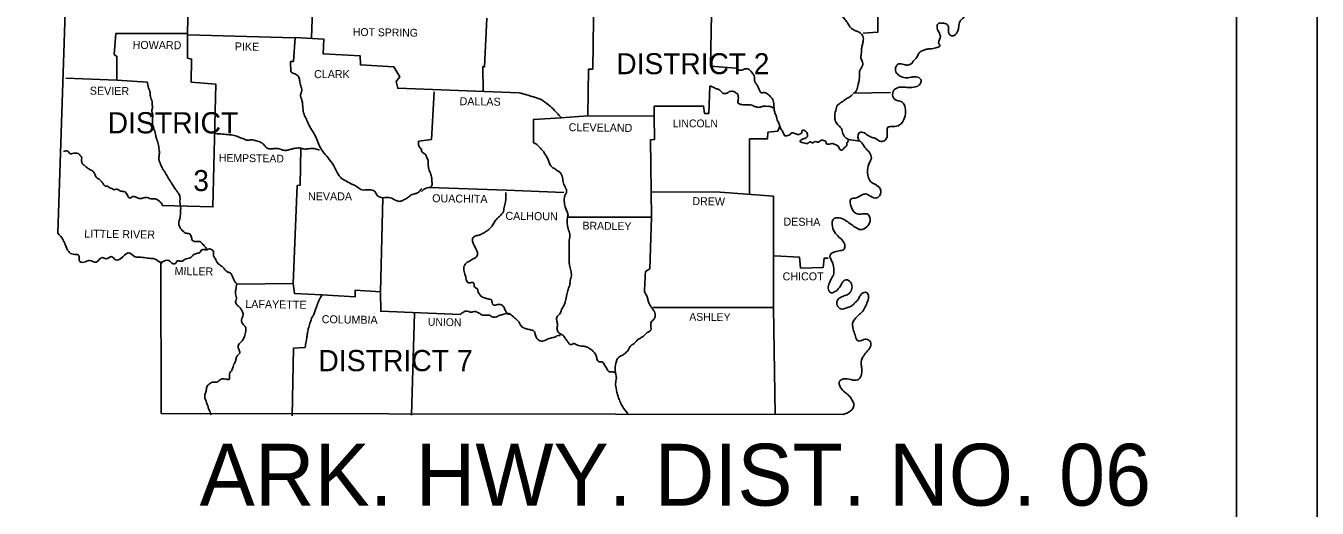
# Model space of a CAD drawing. Extents: x 1367863 to 1368197, y 380048 to 380261.
# Drawn here: x 1368120.7 to 1368196.7, y 380178.3 to 380206.7 of the extents above; entities that cross this region are included whole.
import ezdxf

# ---------------------------------------------------------------- set-up
doc = ezdxf.new("R2010")
doc.units = 0
doc.layers.add('R_Border', color=7, linetype='Continuous')
doc.layers.add('R_No Plot', color=7, linetype='Continuous')

msp = doc.modelspace()

# ---------------------------------------------------------------- linework, layer by layer
at = {"layer": 'R_Border'}
for p, q in [((1368191.969, 380052.084), (1368191.969, 380257.536)), ((1368169.4, 380202.707), (1368171.591, 380202.737)), ((1368169.101, 380199.967), (1368169.788, 380199.877)), ((1368138.078, 380190.782), (1368138.098, 380190.822))]:
    msp.add_line(p, q, dxfattribs=at)
for points in [[(1368123.527, 380224.038), (1368122.546, 380194.468)], [(1368169.987, 380206.243), (1368170.844, 380206.303), (1368170.834, 380208.525), (1368170.037, 380208.585), (1368170.077, 380212.928), (1368169.39, 380213.028), (1368169.36, 380215.957), (1368178.714, 380216.027)], [(1368137.739, 380212.809), (1368137.48, 380205.984)], [(1368130.307, 380211.603), (1368130.187, 380206.214), (1368125.963, 380206.223), (1368125.864, 380204.978), (1368126.023, 380204.869), (1368126.013, 380203.464), (1368123.014, 380203.593)], [(1368154.117, 380208.545), (1368154.057, 380204.121), (1368153.798, 380204.111), (1368153.769, 380201.362)], [(1368161.071, 380208.425), (1368160.981, 380204.301), (1368162.506, 380204.171)], [(1368147.811, 380207.12), (1368147.681, 380204.251), (1368147.582, 380204.281), (1368147.592, 380202.796)], [(1368130.187, 380206.214), (1368130.187, 380204.759), (1368130.427, 380204.709), (1368130.407, 380203.354), (1368131.851, 380203.245), (1368131.682, 380196.002), (1368128.693, 380196.082)], [(1368130.207, 380206.134), (1368136.474, 380205.974)], [(1368136.265, 380203.972), (1368136.245, 380204.57), (1368136.424, 380204.58), (1368136.533, 380205.994), (1368138.217, 380205.885), (1368138.177, 380205.018), (1368140.359, 380204.898), (1368140.369, 380204.37), (1368142.342, 380204.251), (1368142.68, 380203.663), (1368142.471, 380203.394), (1368142.571, 380202.996), (1368149.714, 380202.727)], [(1368126.013, 380203.464), (1368127.826, 380203.354)], [(1368160.951, 380203.125), (1368160.882, 380201.511), (1368160.633, 380201.511), (1368160.583, 380201.94), (1368157.674, 380201.94), (1368157.674, 380201.322)], [(1368144.713, 380202.786), (1368144.553, 380199.967), (1368143.796, 380199.877)], [(1368152.194, 380201.262), (1368150.571, 380201.163), (1368150.561, 380199.788)], [(1368153.769, 380201.362), (1368152.165, 380201.262)], [(1368153.769, 380201.362), (1368157.644, 380201.342)], [(1368157.674, 380201.342), (1368157.684, 380199.967), (1368157.455, 380199.957), (1368157.514, 380195.404)], [(1368165.076, 380200.754), (1368164.946, 380200.465), (1368164.369, 380200.405), (1368164.339, 380200.007), (1368163.293, 380200.007), (1368163.283, 380196.739)], [(1368136.852, 380199.459), (1368136.822, 380197.287), (1368136.633, 380197.257), (1368136.414, 380191.489)], [(1368144.444, 380197.148), (1368148.977, 380196.988), (1368152.344, 380196.859)], [(1368141.684, 380196.54), (1368141.545, 380191.011), (1368140.06, 380191.11), (1368140.05, 380190.712), (1368138.098, 380190.822)], [(1368157.484, 380196.899), (1368161.549, 380196.869), (1368164.707, 380196.63)], [(1368164.707, 380196.63), (1368164.707, 380190.074), (1368164.797, 380183.768)], [(1368152.563, 380195.394), (1368157.514, 380195.404)], [(1368157.514, 380195.404), (1368157.405, 380192.366), (1368157.166, 380192.206)], [(1368128.613, 380192.704), (1368128.633, 380183.838), (1368168.792, 380183.768)], [(1368164.757, 380193.133), (1368166.232, 380193.043), (1368166.291, 380192.406), (1368167.626, 380192.445), (1368167.676, 380192.983), (1368167.925, 380192.983)], [(1368138.098, 380190.822), (1368136.484, 380190.911), (1368136.414, 380191.489), (1368133.086, 380191.449)], [(1368146.237, 380189.676), (1368141.565, 380189.855), (1368141.545, 380190.961)], [(1368143.557, 380189.756), (1368143.378, 380183.738)], [(1368157.584, 380190.084), (1368164.707, 380190.084)], [(1368137.111, 380187.723), (1368136.434, 380187.683), (1368136.354, 380183.708)]]:
    msp.add_lwpolyline(points, dxfattribs=at)
for points in [[(1368178.017, 380213.367), (1368177.768, 380213.058), (1368177.399, 380213.247), (1368177.399, 380213.516), (1368177.449, 380213.785), (1368177.32, 380213.964), (1368177.091, 380213.885), (1368177.091, 380213.546), (1368177.071, 380213.217), (1368177.001, 380212.749), (1368177.15, 380212.599), (1368177.509, 380212.56), (1368177.758, 380212.49), (1368177.907, 380212.241), (1368177.898, 380211.932), (1368177.778, 380211.643), (1368177.609, 380211.394), (1368177.33, 380211.314), (1368177.11, 380211.454), (1368177.021, 380211.743), (1368176.921, 380211.992), (1368176.742, 380212.181), (1368176.543, 380211.972), (1368176.493, 380211.583), (1368176.513, 380211.255), (1368176.513, 380210.806), (1368176.792, 380210.507), (1368176.971, 380210.169), (1368176.911, 380209.86), (1368176.702, 380209.501), (1368176.622, 380209.182), (1368176.533, 380208.754), (1368176.543, 380208.286), (1368176.463, 380207.827), (1368176.314, 380207.519), (1368176.025, 380207.27), (1368175.835, 380207.1), (1368175.686, 380206.941), (1368175.606, 380206.612), (1368175.556, 380206.383), (1368175.347, 380206.104), (1368175.178, 380206.084), (1368175.048, 380206.194), (1368175.008, 380206.383), (1368175.008, 380206.562), (1368174.919, 380206.751), (1368174.65, 380206.831), (1368174.431, 380206.821), (1368174.331, 380206.662), (1368174.47, 380206.233), (1368174.52, 380205.964), (1368174.451, 380205.586), (1368174.49, 380205.546), (1368174.102, 380205.337), (1368173.783, 380205.307), (1368173.514, 380205.227), (1368173.265, 380205.068), (1368173.145, 380204.819), (1368172.966, 380204.63), (1368172.817, 380204.44), (1368172.607, 380204.351)], [(1368166.67, 380209.84), (1368166.7, 380209.392), (1368166.969, 380209.322), (1368167.068, 380209.202), (1368167.128, 380208.953), (1368167.317, 380208.844), (1368167.566, 380208.694), (1368167.716, 380208.585), (1368167.826, 380208.405), (1368167.895, 380208.116), (1368168.075, 380207.937), (1368168.314, 380207.847), (1368168.483, 380207.638), (1368168.593, 380207.339), (1368168.772, 380207.21), (1368168.951, 380206.981), (1368169.031, 380206.881), (1368169.19, 380206.622), (1368169.34, 380206.492), (1368169.449, 380206.413), (1368169.629, 380206.353), (1368169.848, 380206.214), (1368169.987, 380205.994), (1368169.987, 380205.835), (1368169.938, 380205.576), (1368169.888, 380205.317), (1368169.868, 380205.018), (1368169.848, 380204.759), (1368169.948, 380204.54), (1368169.888, 380204.211), (1368169.778, 380204.032), (1368169.768, 380203.793), (1368169.738, 380203.434), (1368169.688, 380203.225), (1368169.599, 380202.886), (1368169.449, 380202.707)], [(1368136.265, 380203.972), (1368136.444, 380203.862), (1368136.653, 380203.763), (1368136.763, 380203.593), (1368136.802, 380203.344), (1368136.882, 380203.065), (1368136.902, 380202.786), (1368136.842, 380202.627), (1368136.922, 380202.278), (1368136.962, 380202.039), (1368136.992, 380201.75), (1368137.081, 380201.372), (1368137.221, 380201.103), (1368137.35, 380200.794), (1368137.57, 380200.445), (1368137.759, 380200.077), (1368137.849, 380199.877), (1368138.008, 380199.479), (1368138.217, 380199.2), (1368138.546, 380198.782), (1368138.845, 380198.353), (1368139.004, 380198.034), (1368139.263, 380197.686), (1368139.542, 380197.516), (1368139.911, 380197.327), (1368140.14, 380197.217), (1368140.399, 380197.028), (1368140.738, 380197.008), (1368140.987, 380197.008), (1368141.226, 380196.909), (1368141.335, 380196.709), (1368141.525, 380196.58), (1368141.684, 380196.54)], [(1368162.506, 380204.171), (1368162.665, 380204.062), (1368162.894, 380204.082), (1368163.054, 380204.141), (1368163.173, 380204.131), (1368163.332, 380204.032), (1368163.442, 380203.902), (1368163.522, 380203.803), (1368163.582, 380203.653), (1368163.582, 380203.504), (1368163.631, 380203.314), (1368163.701, 380203.235), (1368163.781, 380203.095), (1368163.841, 380202.956), (1368163.87, 380202.876), (1368163.99, 380202.727), (1368164.1, 380202.737), (1368164.199, 380202.727), (1368164.339, 380202.657), (1368164.528, 380202.498), (1368164.568, 380202.458), (1368164.697, 380202.169), (1368164.717, 380201.999), (1368164.737, 380201.76), (1368164.787, 380201.541), (1368164.867, 380201.302), (1368164.916, 380201.143), (1368165.016, 380200.913), (1368165.076, 380200.754), (1368165.166, 380200.555), (1368165.295, 380200.336), (1368165.355, 380200.206), (1368165.534, 380200.216)], [(1368172.607, 380204.351), (1368172.378, 380204.39), (1368172.07, 380204.43), (1368171.89, 380204.211), (1368171.95, 380203.892), (1368172.159, 380203.703), (1368172.468, 380203.613), (1368172.787, 380203.643), (1368173.086, 380203.673), (1368173.375, 380203.514), (1368173.325, 380203.225), (1368173.046, 380203.075), (1368172.637, 380203.036), (1368172.309, 380203.065), (1368171.92, 380202.986), (1368171.721, 380202.727), (1368171.83, 380202.348), (1368172.259, 380202.189), (1368172.458, 380201.83), (1368172.468, 380201.491), (1368172.319, 380201.043), (1368172.129, 380200.834), (1368171.741, 380200.744), (1368171.442, 380200.694), (1368171.402, 380200.186), (1368171.273, 380199.937), (1368171.043, 380199.857), (1368170.715, 380200.027), (1368170.515, 380200.097), (1368170.276, 380200.206), (1368169.967, 380200.395), (1368169.738, 380200.366), (1368169.798, 380199.877), (1368169.828, 380199.857), (1368170.087, 380199.499), (1368170.346, 380199.21), (1368170.476, 380198.871)], [(1368127.826, 380203.354), (1368127.886, 380203.026), (1368127.986, 380202.737), (1368127.996, 380202.517), (1368128.095, 380202.189), (1368128.095, 380202.069), (1368128.125, 380201.83), (1368128.085, 380201.701), (1368128.135, 380201.432), (1368128.125, 380201.242), (1368128.125, 380201.073), (1368128.135, 380200.804), (1368128.225, 380200.555), (1368128.314, 380200.196), (1368128.364, 380200.007), (1368128.454, 380199.728), (1368128.514, 380199.379), (1368128.524, 380199.11), (1368128.494, 380198.871), (1368128.564, 380198.602), (1368128.683, 380198.323), (1368128.842, 380198.064), (1368129.022, 380197.765), (1368129.151, 380197.536), (1368129.321, 380197.287), (1368129.45, 380197.078), (1368129.649, 380196.809), (1368129.739, 380196.59), (1368129.739, 380196.281), (1368129.779, 380196.002), (1368129.769, 380195.683), (1368129.749, 380195.394), (1368129.669, 380195.006), (1368129.729, 380194.816), (1368129.938, 380194.548), (1368130.068, 380194.468), (1368130.297, 380194.418), (1368130.407, 380194.269), (1368130.466, 380194.039), (1368130.705, 380193.96), (1368130.955, 380193.94), (1368131.074, 380193.81), (1368131.243, 380193.631), (1368131.293, 380193.541)], [(1368160.951, 380203.125), (1368161.141, 380203.055), (1368161.29, 380202.986), (1368161.469, 380202.916), (1368161.589, 380202.826), (1368161.758, 380202.687), (1368161.958, 380202.707), (1368162.097, 380202.796), (1368162.237, 380202.816), (1368162.346, 380202.806), (1368162.466, 380202.737), (1368162.605, 380202.637), (1368162.625, 380202.498), (1368162.625, 380202.338), (1368162.625, 380202.109), (1368162.705, 380202.069), (1368162.974, 380202.009), (1368163.163, 380202.019), (1368163.332, 380202.019), (1368163.482, 380201.979), (1368163.601, 380201.92), (1368163.691, 380201.9), (1368163.821, 380201.87), (1368163.93, 380201.89), (1368164.119, 380201.93), (1368164.219, 380201.93), (1368164.398, 380201.93), (1368164.508, 380201.92), (1368164.677, 380201.83)], [(1368149.714, 380202.727), (1368150.571, 380202.488), (1368151.009, 380202.328), (1368151.447, 380202.009), (1368151.806, 380201.691), (1368152.165, 380201.282)], [(1368169.38, 380202.637), (1368169.141, 380202.458), (1368168.951, 380202.348), (1368168.742, 380202.189), (1368168.483, 380202.009), (1368168.363, 380201.691), (1368168.304, 380201.252), (1368168.383, 380200.983), (1368168.583, 380200.754), (1368168.722, 380200.575), (1368168.812, 380200.246), (1368169.061, 380200.007), (1368169.131, 380199.977)], [(1368131.831, 380200.326), (1368132.25, 380200.296), (1368132.628, 380200.256), (1368132.927, 380200.216), (1368133.236, 380200.107), (1368133.505, 380200.007), (1368133.684, 380199.937), (1368133.973, 380199.957), (1368134.232, 380199.897), (1368134.511, 380199.808), (1368134.72, 380199.618), (1368134.85, 380199.479), (1368135.109, 380199.419), (1368135.318, 380199.449), (1368135.567, 380199.429), (1368135.856, 380199.339), (1368136.085, 380199.349), (1368136.265, 380199.399), (1368136.484, 380199.449), (1368136.763, 380199.479), (1368136.972, 380199.429), (1368137.241, 380199.419), (1368137.56, 380199.449), (1368137.958, 380199.339)], [(1368165.534, 380200.216), (1368165.674, 380200.276), (1368165.773, 380200.366), (1368165.893, 380200.356), (1368166.022, 380200.306), (1368166.192, 380200.276), (1368166.311, 380200.336), (1368166.361, 380200.385), (1368166.371, 380200.485), (1368166.471, 380200.535), (1368166.58, 380200.465), (1368166.7, 380200.286), (1368166.7, 380200.176), (1368166.66, 380200.107), (1368166.51, 380200.027), (1368166.321, 380199.957), (1368166.261, 380199.877), (1368166.451, 380199.788), (1368166.75, 380199.768), (1368166.819, 380199.838), (1368167.019, 380199.778), (1368167.098, 380199.838), (1368167.357, 380199.828), (1368167.477, 380199.917), (1368167.716, 380199.897), (1368167.796, 380199.848), (1368167.796, 380199.748), (1368167.995, 380199.708), (1368168.134, 380199.738), (1368168.324, 380199.678), (1368168.483, 380199.598), (1368168.573, 380199.479), (1368168.682, 380199.339), (1368168.782, 380199.379), (1368168.862, 380199.479), (1368169.021, 380199.648), (1368169.021, 380199.758), (1368169.071, 380199.838), (1368169.121, 380199.947)], [(1368122.885, 380199.27), (1368123.134, 380199.28), (1368123.293, 380199.13), (1368123.393, 380199.15), (1368123.572, 380199.17), (1368123.732, 380199.16), (1368123.851, 380199.06), (1368123.951, 380198.881), (1368123.941, 380198.722), (1368123.951, 380198.652), (1368124.031, 380198.513), (1368124.16, 380198.403), (1368124.3, 380198.293), (1368124.429, 380198.204), (1368124.648, 380198.064), (1368124.678, 380198.014), (1368124.758, 380197.845), (1368124.867, 380197.696), (1368125.007, 380197.616), (1368125.146, 380197.457), (1368125.206, 380197.397), (1368125.326, 380197.237), (1368125.445, 380197.227), (1368125.605, 380197.128), (1368125.724, 380197.098), (1368125.854, 380197.008), (1368125.993, 380197.048), (1368126.153, 380196.988), (1368126.372, 380196.919), (1368126.491, 380196.899), (1368126.641, 380196.689), (1368126.78, 380196.52), (1368126.95, 380196.61), (1368127.278, 380196.52), (1368127.488, 380196.5), (1368127.677, 380196.56), (1368127.816, 380196.55), (1368128.085, 380196.48), (1368128.245, 380196.48), (1368128.424, 380196.42), (1368128.583, 380196.281), (1368128.693, 380196.142), (1368128.693, 380196.082)], [(1368143.796, 380199.877), (1368143.796, 380199.668), (1368143.876, 380199.479), (1368143.956, 380199.389), (1368143.985, 380199.24), (1368144.085, 380199.18), (1368144.224, 380199.051), (1368144.304, 380198.861), (1368144.354, 380198.742), (1368144.354, 380198.582), (1368144.364, 380198.433), (1368144.394, 380198.244), (1368144.523, 380197.915), (1368144.553, 380197.785), (1368144.573, 380197.676), (1368144.583, 380197.486), (1368144.583, 380197.267), (1368144.444, 380197.148)], [(1368150.561, 380199.788), (1368150.81, 380199.628), (1368151.019, 380199.409), (1368151.168, 380199.24), (1368151.268, 380199.06), (1368151.407, 380198.841), (1368151.587, 380198.423), (1368151.756, 380198.283), (1368151.985, 380198.134), (1368152.125, 380198.034), (1368152.264, 380197.726), (1368152.334, 380197.407), (1368152.453, 380197.118), (1368152.513, 380196.899), (1368152.414, 380196.679), (1368152.384, 380196.241), (1368152.453, 380195.942), (1368152.543, 380195.723), (1368152.593, 380195.474), (1368152.563, 380195.394)], [(1368170.476, 380198.871), (1368170.356, 380198.622), (1368170.236, 380198.184), (1368170.276, 380197.805), (1368170.436, 380197.486), (1368170.705, 380197.317), (1368170.984, 380197.068), (1368170.964, 380196.679), (1368170.794, 380196.54), (1368170.416, 380196.64), (1368170.117, 380196.769), (1368169.868, 380196.689), (1368169.529, 380196.53), (1368169.28, 380196.49), (1368169.29, 380195.972), (1368169.629, 380195.594), (1368169.918, 380195.594), (1368170.266, 380195.554), (1368170.386, 380195.155), (1368170.187, 380194.826), (1368169.858, 380194.667), (1368169.439, 380194.856), (1368169.141, 380195.066), (1368168.852, 380195.265), (1368168.473, 380195.364), (1368168.264, 380195.325), (1368168.164, 380194.856), (1368168.344, 380194.448), (1368168.632, 380194.159), (1368168.891, 380193.79), (1368168.852, 380193.511), (1368168.652, 380193.432), (1368168.304, 380193.362), (1368168.094, 380193.252), (1368168.035, 380193.163), (1368168.144, 380192.794), (1368168.244, 380192.386), (1368168.244, 380192.077), (1368168.124, 380191.788), (1368167.935, 380191.35), (1368167.965, 380191.071), (1368168.094, 380190.941), (1368168.254, 380190.981), (1368168.473, 380191.13), (1368168.623, 380191.31), (1368168.742, 380191.529), (1368168.971, 380191.718), (1368169.25, 380191.549), (1368169.32, 380191.21), (1368169.16, 380190.911), (1368168.921, 380190.782), (1368168.642, 380190.672), (1368168.433, 380190.433), (1368168.483, 380190.144), (1368168.652, 380189.995), (1368169.061, 380190.074), (1368169.33, 380190.194), (1368169.479, 380190.343), (1368169.669, 380190.533), (1368169.768, 380190.722), (1368169.908, 380190.911)], [(1368143.995, 380197.098), (1368143.876, 380196.958), (1368143.736, 380196.829), (1368143.567, 380196.779), (1368143.418, 380196.739), (1368143.218, 380196.6), (1368143.059, 380196.49), (1368142.86, 380196.391), (1368142.66, 380196.331), (1368142.421, 380196.41), (1368142.282, 380196.48), (1368142.142, 380196.54), (1368141.684, 380196.54)], [(1368143.956, 380196.919), (1368144.234, 380197.108), (1368144.553, 380197.148)], [(1368148.937, 380196.859), (1368148.917, 380196.311), (1368148.837, 380195.972), (1368148.757, 380195.663), (1368148.598, 380195.484), (1368148.419, 380195.315), (1368148.259, 380195.115), (1368148.12, 380194.876), (1368147.97, 380194.717), (1368147.781, 380194.567), (1368147.602, 380194.458), (1368147.393, 380194.358), (1368147.163, 380194.298), (1368146.994, 380194.179), (1368146.984, 380193.92), (1368147.173, 380193.541), (1368147.243, 380193.372), (1368147.263, 380193.163), (1368147.183, 380193.043), (1368147.004, 380192.944), (1368146.805, 380192.824), (1368146.615, 380192.714), (1368146.486, 380192.525), (1368146.456, 380192.276), (1368146.546, 380191.977), (1368146.586, 380191.808), (1368146.725, 380191.529), (1368146.835, 380191.539), (1368147.034, 380191.529), (1368147.054, 380191.479), (1368147.064, 380191.419), (1368147.104, 380191.28), (1368147.273, 380191.16), (1368147.293, 380191.051), (1368147.393, 380190.841), (1368147.552, 380190.692), (1368147.681, 380190.652), (1368147.931, 380190.572), (1368148.06, 380190.543), (1368148.2, 380190.224), (1368148.379, 380190.234), (1368148.508, 380190.254), (1368148.728, 380190.204), (1368148.827, 380190.074), (1368148.927, 380189.855), (1368149.056, 380189.696), (1368149.146, 380189.696)], [(1368152.563, 380195.394), (1368152.603, 380194.717), (1368152.703, 380194.388), (1368152.673, 380194.039), (1368152.663, 380193.701), (1368152.663, 380193.392), (1368152.663, 380193.093), (1368152.663, 380192.794), (1368152.683, 380192.575), (1368152.762, 380192.256), (1368152.792, 380191.957), (1368152.732, 380191.668), (1368152.693, 380191.409), (1368152.603, 380191.15), (1368152.533, 380190.851), (1368152.444, 380190.463), (1368152.364, 380190.214), (1368152.214, 380189.955), (1368152.115, 380189.706), (1368151.965, 380189.556), (1368151.935, 380189.297), (1368151.975, 380189.048), (1368151.945, 380188.829), (1368152.025, 380188.63), (1368152.224, 380188.48)], [(1368122.546, 380194.468), (1368122.865, 380194.049), (1368122.995, 380193.751), (1368123.184, 380193.372), (1368123.453, 380193.213), (1368123.772, 380193.163), (1368123.841, 380192.794), (1368124.17, 380192.774), (1368124.429, 380192.854), (1368124.798, 380192.754), (1368125.176, 380193.023), (1368125.395, 380192.954), (1368125.714, 380193.083), (1368125.953, 380192.884), (1368126.372, 380193.063), (1368126.74, 380193.302), (1368127.099, 380193.073), (1368127.438, 380193.043), (1368127.836, 380192.983), (1368128.155, 380192.963), (1368128.444, 380192.824), (1368128.653, 380192.685), (1368128.613, 380192.704)], [(1368128.613, 380192.704), (1368128.992, 380192.864), (1368129.151, 380192.814), (1368129.301, 380192.665), (1368129.46, 380192.665), (1368129.55, 380192.804), (1368129.719, 380192.814), (1368129.849, 380192.804), (1368129.988, 380192.884), (1368130.108, 380192.944), (1368130.277, 380192.993), (1368130.397, 380193.043), (1368130.506, 380193.163), (1368130.705, 380193.262), (1368130.935, 380193.342), (1368130.994, 380193.452), (1368131.104, 380193.491), (1368131.323, 380193.482), (1368131.473, 380193.541), (1368131.592, 380193.491), (1368131.702, 380193.412), (1368131.722, 380193.133), (1368131.811, 380192.973), (1368131.941, 380192.704), (1368132.13, 380192.555), (1368132.299, 380192.416), (1368132.369, 380192.326), (1368132.558, 380192.166), (1368132.718, 380192.107), (1368132.798, 380191.987), (1368132.917, 380191.708), (1368133.086, 380191.449)], [(1368157.166, 380192.206), (1368157.136, 380191.868), (1368157.126, 380191.549), (1368157.106, 380191.24), (1368157.106, 380191.011), (1368157.235, 380190.762), (1368157.305, 380190.523), (1368157.385, 380190.313), (1368157.544, 380190.035), (1368157.684, 380189.835), (1368157.724, 380189.536), (1368157.634, 380189.377), (1368157.475, 380189.148), (1368157.465, 380188.739), (1368157.265, 380188.6), (1368157.016, 380188.381), (1368156.867, 380188.281), (1368156.717, 380188.191), (1368156.548, 380188.012), (1368156.309, 380187.843), (1368156.14, 380187.574), (1368155.94, 380187.365), (1368155.771, 380187.255), (1368155.542, 380187.116), (1368155.442, 380186.896), (1368155.372, 380186.488), (1368155.402, 380186.189), (1368155.442, 380185.93), (1368155.392, 380185.601), (1368155.442, 380185.243), (1368155.502, 380184.954), (1368155.592, 380184.705), (1368155.711, 380184.416), (1368155.861, 380184.157), (1368156.189, 380183.748)], [(1368133.086, 380191.449), (1368133.027, 380191.13), (1368133.017, 380190.881), (1368133.067, 380190.582), (1368133.017, 380190.443), (1368133.096, 380190.234), (1368133.266, 380190.074), (1368133.385, 380189.895), (1368133.465, 380189.646), (1368133.365, 380189.357), (1368133.475, 380189.068), (1368133.575, 380188.959), (1368133.624, 380188.779), (1368133.555, 380188.441), (1368133.455, 380188.191), (1368133.236, 380187.932), (1368133.166, 380187.813), (1368133.196, 380187.653), (1368133.256, 380187.385), (1368133.196, 380187.315), (1368133.057, 380187.125), (1368133.017, 380186.916), (1368132.917, 380186.737), (1368132.808, 380186.418), (1368132.658, 380186.159), (1368132.638, 380185.86), (1368132.419, 380185.86), (1368132.17, 380185.86), (1368131.941, 380185.701), (1368131.732, 380185.691), (1368131.483, 380185.591), (1368131.323, 380185.382), (1368131.273, 380185.153), (1368131.204, 380184.934), (1368131.273, 380184.555), (1368131.373, 380184.296), (1368131.443, 380184.087), (1368131.582, 380183.748)], [(1368169.908, 380190.911), (1368170.167, 380190.971), (1368170.286, 380190.802), (1368170.236, 380190.433), (1368170.087, 380190.084), (1368169.878, 380189.785), (1368169.649, 380189.576), (1368169.36, 380189.128), (1368169.419, 380188.71), (1368169.529, 380188.371), (1368169.679, 380188.112), (1368169.948, 380188.162), (1368170.236, 380188.201), (1368170.416, 380188.052), (1368170.396, 380187.753), (1368170.177, 380187.454), (1368169.967, 380187.165), (1368169.858, 380186.777), (1368169.898, 380186.498), (1368169.898, 380186.249), (1368169.818, 380185.97), (1368169.659, 380185.82), (1368169.25, 380185.83), (1368168.822, 380185.87), (1368168.593, 380185.741), (1368168.642, 380185.372), (1368168.891, 380185.093), (1368169.071, 380184.954), (1368169.32, 380184.645), (1368169.429, 380184.396), (1368169.4, 380184.177), (1368169.24, 380183.987), (1368168.792, 380183.768)], [(1368137.111, 380187.723), (1368137.171, 380188.082), (1368137.221, 380188.351), (1368137.251, 380188.61), (1368137.321, 380188.909), (1368137.42, 380189.228), (1368137.51, 380189.487), (1368137.629, 380189.676), (1368137.699, 380189.895), (1368137.799, 380190.164), (1368137.898, 380190.433), (1368138.078, 380190.782)], [(1368146.237, 380189.676), (1368146.416, 380189.795), (1368146.586, 380189.865), (1368146.745, 380189.835), (1368146.924, 380189.805), (1368147.074, 380189.835), (1368147.273, 380189.795), (1368147.432, 380189.696), (1368147.622, 380189.626), (1368147.811, 380189.626), (1368147.97, 380189.626), (1368148.12, 380189.526), (1368148.379, 380189.536), (1368148.598, 380189.626), (1368148.817, 380189.686), (1368149.116, 380189.726), (1368149.375, 380189.536), (1368149.564, 380189.377), (1368149.714, 380189.208), (1368149.823, 380189.008), (1368149.943, 380188.899), (1368150.142, 380188.819), (1368150.292, 380188.789), (1368150.481, 380188.739), (1368150.581, 380188.69), (1368150.67, 380188.48), (1368150.81, 380188.201), (1368151.089, 380188.102), (1368151.427, 380188.231), (1368151.696, 380188.311), (1368151.896, 380188.371), (1368152.015, 380188.421), (1368152.125, 380188.431), (1368152.095, 380188.451), (1368152.224, 380188.48), (1368152.344, 380188.391), (1368152.424, 380188.271), (1368152.553, 380188.102), (1368152.673, 380187.942), (1368152.792, 380187.893), (1368152.912, 380187.952), (1368153.081, 380187.903), (1368153.221, 380187.843), (1368153.39, 380187.803), (1368153.529, 380187.793), (1368153.719, 380187.753), (1368153.858, 380187.673), (1368153.988, 380187.594), (1368154.117, 380187.454), (1368154.257, 380187.235), (1368154.297, 380187.056), (1368154.446, 380186.886), (1368154.595, 380186.886), (1368154.795, 380186.597), (1368154.874, 380186.488), (1368155.044, 380186.289), (1368155.163, 380186.289), (1368155.392, 380186.249)]]:
    msp.add_spline(points, degree=3, dxfattribs=at)
at = {"layer": 'R_No Plot'}
msp.add_lwpolyline([(1367863.393, 380261.431), (1368196.721, 380261.431), (1368196.721, 380048.101), (1367863.393, 380048.101)], close=True, dxfattribs=at)

# ---------------------------------------------------------------- texts
at = {"layer": 'R_Border'}
for s, height, rotation, p in [('HOT SPRING', 0.4603, 359.22157, (1368139.921, 380206.084)), ('HOWARD', 0.4713, 359.51446, (1368126.95, 380205.317)), ('PIKE', 0.4711, 359.04516, (1368132.967, 380205.227)), ('SEVIER', 0.4713, 359.42706, (1368124.429, 380202.617)), ('DALLAS', 0.4711, 359.24615, (1368146.207, 380201.999)), ('CLEVELAND', 0.4713, 359.33765, (1368152.633, 380200.465)), ('HEMPSTEAD', 0.4601, 359.1885, (1368132.03, 380198.672)), ('OUACHITA', 0.4713, 359.20428, (1368144.593, 380196.281)), ('DREW', 0.4711, 359.22578, (1368159.915, 380196.112)), ('CALHOUN', 0.4713, 359.36341, (1368148.907, 380195.245)), ('BRADLEY', 0.4601, 359.1449, (1368153.45, 380194.677)), ('DESHA', 0.4711, 359.3704, (1368165.285, 380194.906)), ('LITTLE RIVER', 0.47126, 359.16968, (1368124.1, 380194.199)), ('MILLER', 0.4711, 359.13195, (1368129.42, 380191.997)), ('LAFAYETTE', 0.4711, 359.18387, (1368133.585, 380190.054)), ('COLUMBIA', 0.4711, 359.21248, (1368138.088, 380189.158)), ('UNION', 0.4603, 358.95837, (1368144.334, 380189.008)), ('ASHLEY', 0.4603, 359.2361, (1368159.736, 380189.307))]:
    msp.add_text(s, height=height, rotation=rotation, dxfattribs=at).set_placement(p)
for s, height, p in [('DISTRICT 2', 1.2383, (1368155.442, 380203.823)), ('CLARK', 0.4712, (1368137.639, 380203.593)), ('DISTRICT', 1.2493, (1368125.475, 380200.336)), ('LINCOLN', 0.4603, (1368158.76, 380200.694)), ('3', 1.238, (1368130.526, 380196.938)), ('NEVADA', 0.4712, (1368137.281, 380196.391)), ('CHICOT', 0.4712, (1368165.235, 380191.678)), ('DISTRICT 7', 1.2493, (1368137.888, 380186.328)), ('ARK. HWY. DIST. NO. 06', 3.64368, (1368130.896, 380178.408))]:
    msp.add_text(s, height=height, dxfattribs=at).set_placement(p)

doc.saveas('drawing.dxf')
